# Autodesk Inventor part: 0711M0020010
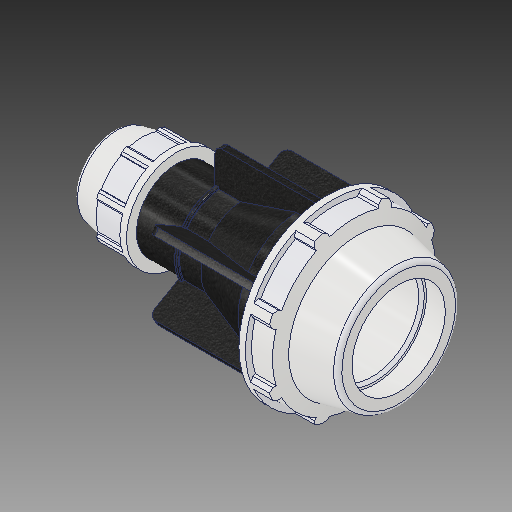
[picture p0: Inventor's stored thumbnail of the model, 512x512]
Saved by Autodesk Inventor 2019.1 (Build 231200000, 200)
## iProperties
Created: 2017-02
Part Number: 0711M0020010
Material: PVC-Piping
Description: PLASSON REDUCING COUPLER 2'' - 1''
Document SubType Name: Modeling
Designer: KIM
Mass: 92.6774 g
Surface Area: 199.44 cm^2
Volume: 66.1981 cm^3
Density: 1.4 g/cm^3
Appearance: PTFE
Author: KIM
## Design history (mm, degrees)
derived "0711M0.ipt"
feature "Solid1::0711M0.ipt"
tag "TaggingFeature1"
body "Solid1"
other parameters: "d2" = 60.1, "d4" = 15.33333, "d5" = 26.28571, "d7" = 113.03, "d9" = 26.28571, "d11" = 2.62857, "d12" = 90.424, "d13" = 120 deg, "d14" = 78.13, "d15" = 12 deg, "d16" = 101.727, "d18" = 3.005, "d19" = 35 deg, "d20" = 17.5 deg, "d21" = 105.1179, "d23" = 0, "d25" = 360 deg, "d27" = 2.2606, "d42" = 20.24, "d46" = 1.803, "d51" = 184, "d52" = 63.44828, "d53" = 12 deg, "d54" = 64.008, "d56" = 49.95, "d57" = 33.3, "d58" = 54.09, "d59" = 29.97, "d60" = 57.6072, "d61" = 51.2064, "d62" = 18.4, "d63" = 22.08, "d64" = 120 deg, "d65" = 64.008, "d68" = 13.14286, "d74" = 59.52744, "d75" = 35 deg, "d76" = 17.5 deg, "d78" = 0, "d80" = 360 deg, "d85" = 1.28016, "d88" = 0.666, "d93" = 84, "d94" = 79.121, "d97" = 3.61683, "d98" = 4.2672, "d99" = 0, "d100" = 4.5212, "d102" = 360 deg, "d104" = 2, "d106" = 0, "d107" = 4.2672, "d108" = 0, "d109" = 4.2672, "d110" = 0, "d_" = 60.1, "E_" = 113.03, "H_" = 184, "l_" = 64.008, "d_1" = 33.3, "E_1" = 64.008, "l_1" = 84, "d96" = 10.8505
